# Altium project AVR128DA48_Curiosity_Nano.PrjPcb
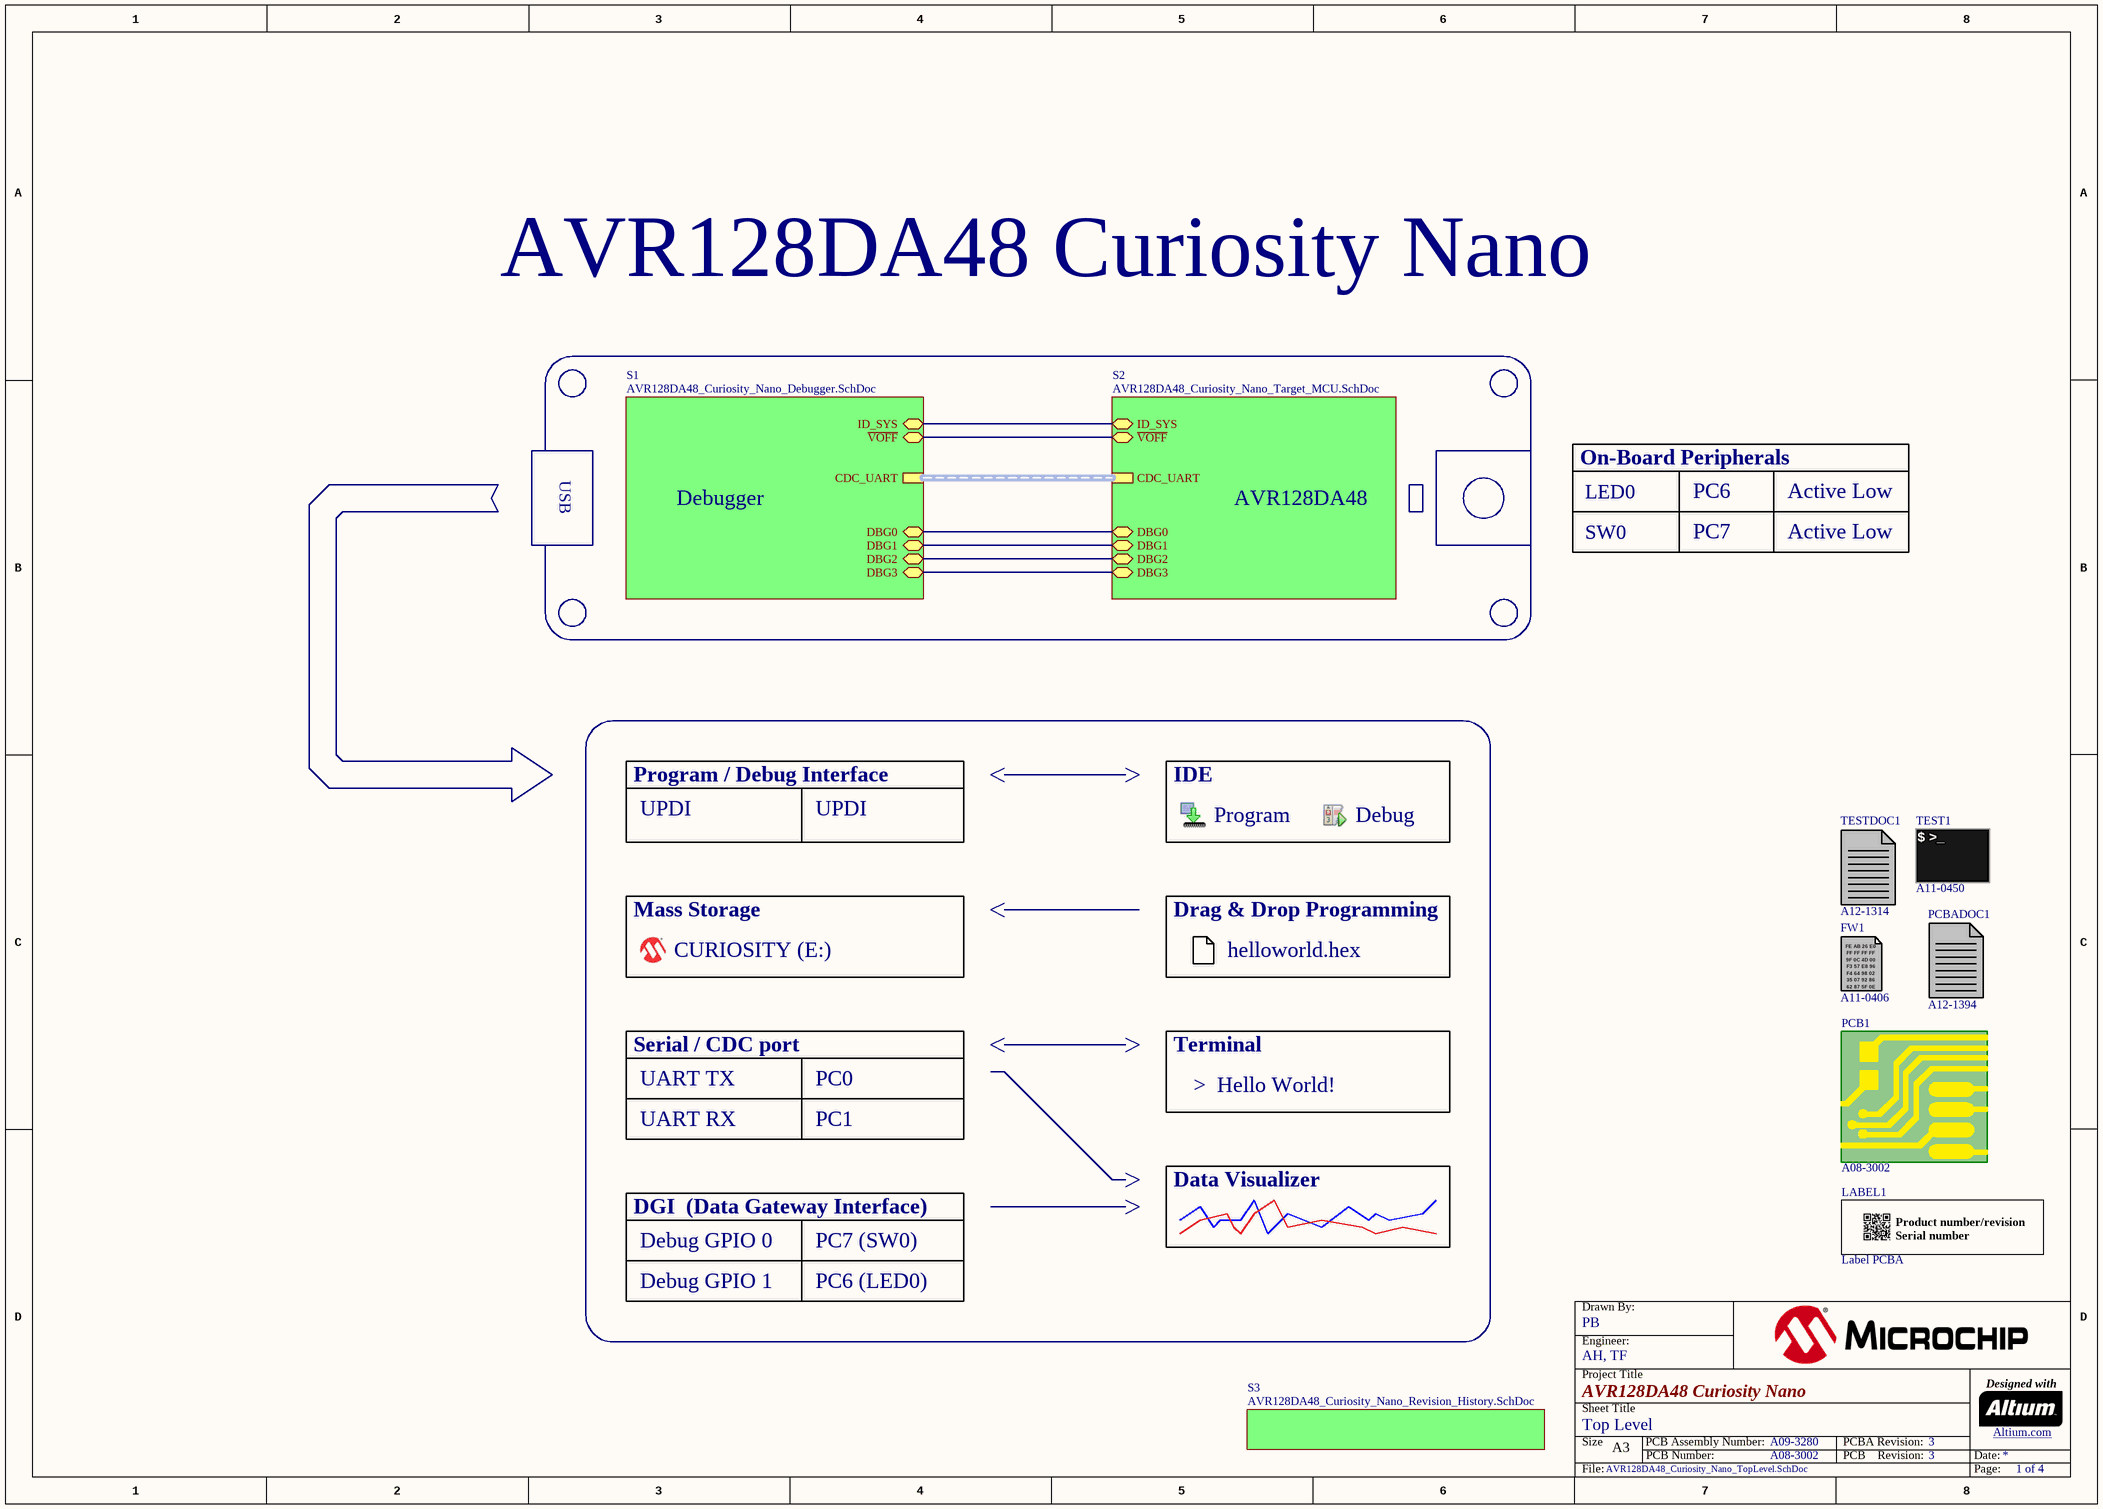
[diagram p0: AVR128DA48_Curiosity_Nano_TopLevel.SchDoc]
4 sheets, 71 parts. Net scope: hierarchical (ports join the sheet entries above them; power ports are global).
Board file: AVR128DA48_Curiosity_Nano.PcbDoc
Sheets:
  AVR128DA48_Curiosity_Nano_TopLevel.SchDoc
    S2 = AVR128DA48_Curiosity_Nano_Target_MCU.SchDoc
    S1 = AVR128DA48_Curiosity_Nano_Debugger.SchDoc
    S3 = AVR128DA48_Curiosity_Nano_Revision_History.SchDoc

## Sheet AVR128DA48_Curiosity_Nano_TopLevel.SchDoc: Top Level
size A3; Organization: Microchip Norway; Address1: Brøsetvegen 164; Address2: 7069 Trondheim; Address3: NORWAY; DocumentNumber: A09-3280; Revision: 3; SheetNumber: 1; SheetTotal: 4; DrawnBy: PB; Engineer: AH, TF; PageSetup: Record=PageOptions¦CenterHorizontal=True¦CenterVertical=True¦PrintScale=1.01¦XCorrection=1.00¦YCorrection=1.00¦PrintKind=1¦BorderSize=5000000¦LeftOffset=0¦BottomOffset=0¦Orientation=2¦PaperLength=1000¦PaperWidth=1000¦Scale=100¦PaperSource=7¦PrintQuality=-4¦MediaType=1¦DitherType=10¦PaperKind=A3 (297 x 420 mm)¦PrintScaleMode=1; ProjectTitle: AVR128DA48 Curiosity Nano; PCBNumber: A08-3002; PCBRevision: 3

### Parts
FW1  AN: A11-0406  (mechanical)
LABEL1  value Label PCBA  [AP8-00317]
PCB1  AN: A08-3002  (mechanical)
PCBADOC1  AN: A12-1394  (mechanical)
TEST1  AN: A11-0450  (mechanical)
TESTDOC1  AN: A12-1314  (hidden comment: Use test fixture A13-0177)  (mechanical)

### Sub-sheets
S1 = AVR128DA48_Curiosity_Nano_Debugger.SchDoc: CDC_UART (harness UART), DBG2 (bidir), DBG1 (bidir), DBG3 (bidir), DBG0 (bidir), ~{VOFF} (bidir), ID_SYS (bidir)
S2 = AVR128DA48_Curiosity_Nano_Target_MCU.SchDoc: DBG0 (bidir), CDC_UART (harness UART), DBG1 (bidir), DBG3 (bidir), DBG2 (bidir), ~{VOFF} (bidir), ID_SYS (bidir)
S3 = AVR128DA48_Curiosity_Nano_Revision_History.SchDoc: no entries

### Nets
DBG0: sheet S2/DBG0, sheet S1/DBG0
DBG1: sheet S2/DBG1, sheet S1/DBG1
DBG2: sheet S2/DBG2, sheet S1/DBG2
DBG3: sheet S2/DBG3, sheet S1/DBG3
ID_SYS: sheet S2/ID_SYS, sheet S1/ID_SYS
~{VOFF}: sheet S2/~{VOFF}, sheet S1/~{VOFF}

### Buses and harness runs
harness sheet S1/CDC_UART = sheet S2/CDC_UART

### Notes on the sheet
- AVR128DA48 Curiosity Nano
- USB
- Debugger
- AVR128DA48
- On-Board Peripherals
- LED0
- PC6
- Active Low
- SW0
- PC7
- Program / Debug Interface
- IDE
- UPDI
- Program
- Debug
- Mass Storage
- Drag & Drop Programming
- CURIOSITY (E:)
- helloworld.hex
- Serial / CDC port
- Terminal
- UART TX
- UART RX
- PC1
- PC0
- >  Hello World!
- Data Visualizer
- DGI  (Data Gateway Interface)
- Debug GPIO 0
- PC7 (SW0)
- Debug GPIO 1
- PC6 (LED0)

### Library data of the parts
FW1 = A11-0406: nEDBG firmware; PartGroup: Software,Firmware,Tools
LABEL1 = A09-0611: PCBA identification label PP Top White Gloss; Manufacturer: ACT Logimark AS; MPN: 505462; PartGroup: Mechanical devices,Packaging materials,Printed Labels,PCBA
PCB1 = A08-3002: AVR128DA48 Curiosity Nano PCB documentation; PartGroup: Mechanical devices,Printed circuit boards
PCBADOC1 = A12-1394: AVR128DA48 Curiosity Nano PCBA documentation; PartGroup: Documentation,PCBA Documents,Atmel; Value: A09-3280 PCBA files
TEST1 = A11-0450: Fixture test for AVR128DA48 Curiosity Nano; PartGroup: Software,Test software,Starter Kit; Value: AVR128DA48 Curiosity Nano test
TESTDOC1 = A12-1314: Generic Test Instructions for Curiosity Nano; PartGroup: Documentation,Procedures,Test Instructions; Value: Curiosity Nano Test Instructions

## Sheet AVR128DA48_Curiosity_Nano_Target_MCU.SchDoc: Target MCU
size A3; Organization: Microchip Norway; Address1: Brøsetvegen 164; Address2: 7069 Trondheim; Address3: NORWAY; DocumentNumber: A09-3280; Revision: 3; SheetNumber: 2; SheetTotal: 4; DrawnBy: PB; Engineer: AH, TF; PageSetup: Record=PageOptions¦CenterHorizontal=True¦CenterVertical=True¦PrintScale=1.01¦XCorrection=1.00¦YCorrection=1.00¦PrintKind=1¦BorderSize=5000000¦LeftOffset=0¦BottomOffset=0¦Orientation=2¦PaperLength=1000¦PaperWidth=1000¦Scale=100¦PaperSource=7¦PrintQuality=-4¦MediaType=1¦DitherType=10¦PaperKind=A3 (297 x 420 mm)¦PrintScaleMode=1; ProjectTitle: AVR128DA48 Curiosity Nano; PCBNumber: A08-3002; PCBRevision: 3
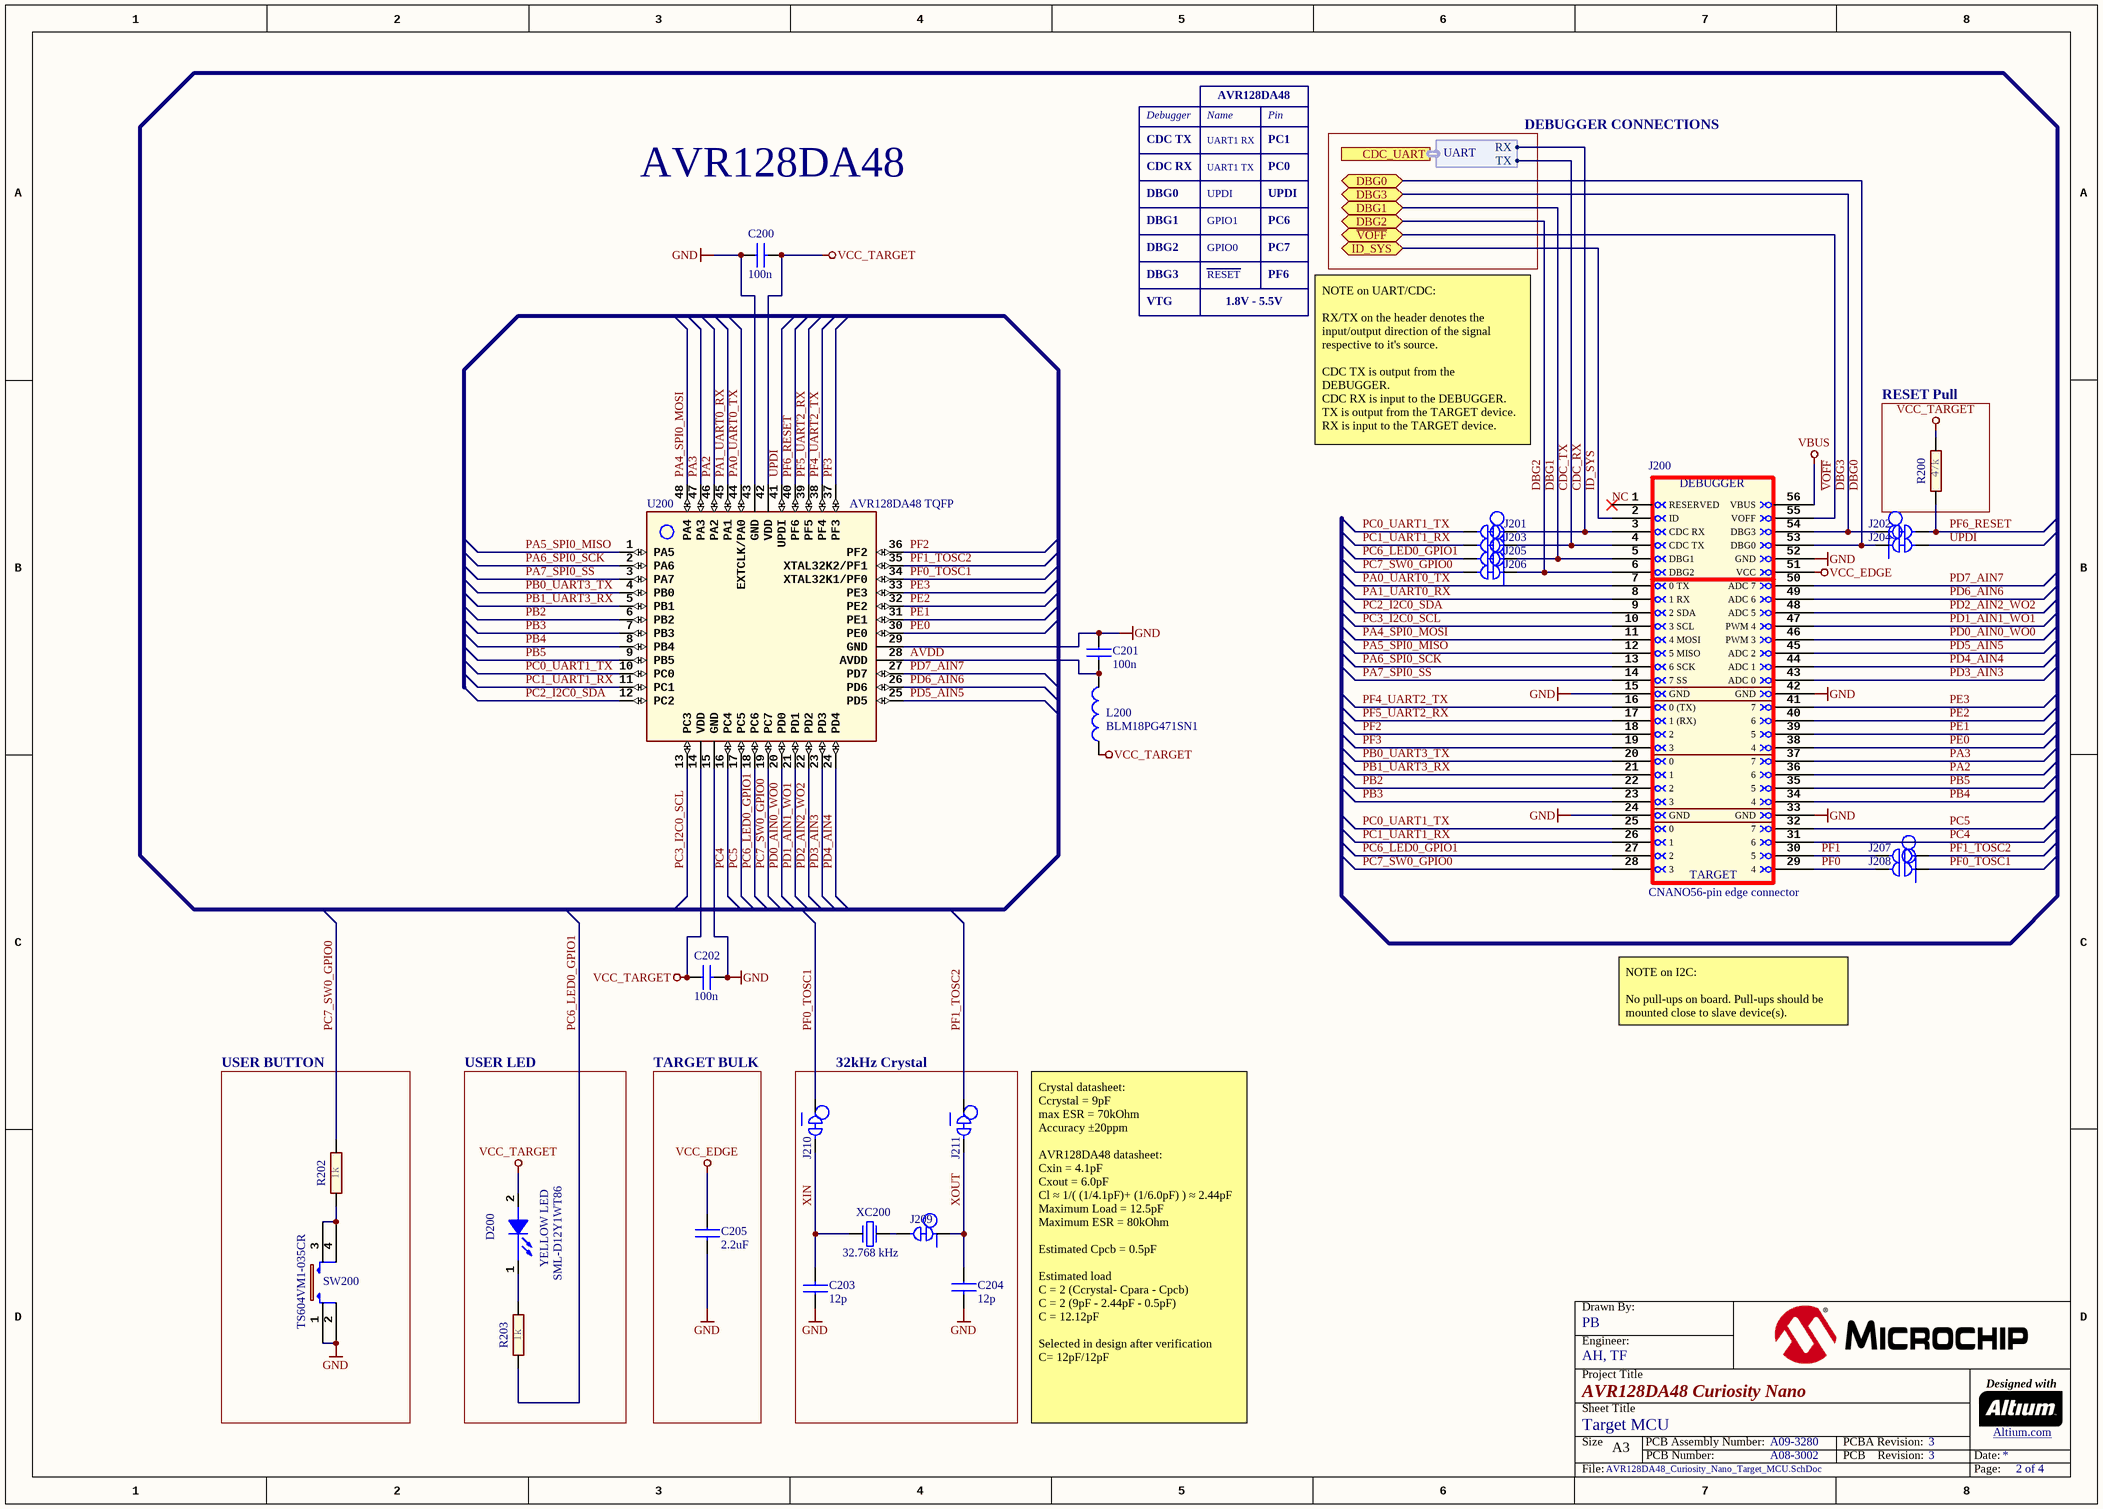
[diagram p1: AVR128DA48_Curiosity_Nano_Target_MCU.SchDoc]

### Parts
C200  value 100n  [AP1-00053]
C201  value 100n  [AP1-00053]
C202  value 100n  [AP1-00053]
C203  value 12p  [AP1-00001]
C204  value 12p  [AP1-00001]
C205  value 2.2uF  [AP1-00053]
D200  value YELLOW LED  MPN: SML-D12Y1WT86  [AP4-00169]
J200  value CNANO56-pin edge connector  [AP8-01100]  (no BOM)
J201  (no value)  [AP8-01166]  (net tie, no BOM)
J202  (no value)  [AP8-01166]  (net tie, no BOM)
J203  (no value)  [AP8-01166]  (net tie, no BOM)
J204  (no value)  [AP8-01166]  (net tie, no BOM)
J205  (no value)  [AP8-01166]  (net tie, no BOM)
J206  (no value)  [AP8-01166]  (net tie, no BOM)
J207  (no value)  [AP9-00172]  (no BOM)
J208  (no value)  [AP9-00172]  (no BOM)
J209  (no value)  [AP8-00595]  (net tie, no BOM)
J210  (no value)  [AP8-01166]  (net tie, no BOM)
J211  (no value)  [AP8-01166]  (net tie, no BOM)
L200  value BLM18PG471SN1  [AP3-00005]
R200  value 47k  [AP2-00011]
R202  value 1k  [AP2-00011]
R203  value 1k  [AP2-00011]
SW200  value TS604VM1-035CR  [AP8-00137]  (hidden comment: Rating: DC 12V 50mA / Max 0.1 ohm contact resistance)
U200  value AVR128DA48 TQFP  [AP6-00357]
XC200  (no value)  [AP7-00069]

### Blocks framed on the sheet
RESET Pull: R200
USER BUTTON: R202 SW200
USER LED: D200 R203
TARGET BULK: C205
32kHz Crystal: C203 C204 J209-J211 XC200

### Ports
CDC_UART (harness UART), DBG0 (bidir), DBG1 (bidir), DBG2 (bidir), DBG3 (bidir), ID_SYS (bidir), ~{VOFF} (bidir)

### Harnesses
UART: TX, RX

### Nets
GND: C200.1 C201.1 C202.2 C203.1 C204.2 C205.2 J200.15(GND) J200.24(GND) J200.33(GND) J200.42(GND) J200.52(GND) SW200.1 SW200.2 U200.15(GND) U200.29(GND) U200.43(GND)
VBUS: J200.56(VBUS)
VCC_EDGE: C205.1 J200.51(VCC)
VCC_TARGET: C200.2 C202.1 D200.2(ANODE) L200.1 R200.1 U200.14(VDD) U200.42(VDD)
AVDD: C201.2 L200.2 U200.28(AVDD)
CDC_RX: J200.3(CDC_RX) J201.1 ; port CDC_UART.RX
CDC_TX: J200.4(CDC_TX) J203.1 ; port CDC_UART.TX
DBG0: J200.53(DBG0) J204.1 ; port DBG0
DBG1: J200.5(DBG1) J205.1 ; port DBG1
DBG2: J200.6(DBG2) J206.1 ; port DBG2
DBG3: J200.54(DBG3) J202.1 ; port DBG3
ID_SYS: J200.2(ID) ; port ID_SYS
NC: J200.1(RESERVED)
PA0_UART0_TX: J200.7(0_TX) U200.44(EXTCLK/PA0)
PA1_UART0_RX: J200.8(1_RX) U200.45(PA1)
PA2: J200.36(6) U200.46(PA2)
PA3: J200.37(7) U200.47(PA3)
PA4_SPI0_MOSI: J200.11(4_MOSI) U200.48(PA4)
PA5_SPI0_MISO: J200.12(5_MISO) U200.1(PA5)
PA6_SPI0_SCK: J200.13(6_SCK) U200.2(PA6)
PA7_SPI0_SS: J200.14(7_SS) U200.3(PA7)
PB0_UART3_TX: J200.20(0) U200.4(PB0)
PB1_UART3_RX: J200.21(1) U200.5(PB1)
PB2: J200.22(2) U200.6(PB2)
PB3: J200.23(3) U200.7(PB3)
PB4: J200.34(4) U200.8(PB4)
PB5: J200.35(5) U200.9(PB5)
PC0_UART1_TX: J200.25(0) J201.2 U200.10(PC0)
PC1_UART1_RX: J200.26(1) J203.2 U200.11(PC1)
PC2_I2C0_SDA: J200.9(2_SDA) U200.12(PC2)
PC3_I2C0_SCL: J200.10(3_SCL) U200.13(PC3)
PC4: J200.31(6) U200.16(PC4)
PC5: J200.32(7) U200.17(PC5)
PC6_LED0_GPIO1: J200.27(2) J205.2 R203.1 U200.18(PC6)
PC7_SW0_GPIO0: J200.28(3) J206.2 R202.1 U200.19(PC7)
PD0_AIN0_WO0: J200.46(PWM_3) U200.20(PD0)
PD1_AIN1_WO1: J200.47(PWM_4) U200.21(PD1)
PD2_AIN2_WO2: J200.48(ADC_5) U200.22(PD2)
PD3_AIN3: J200.43(ADC_0) U200.23(PD3)
PD4_AIN4: J200.44(ADC_1) U200.24(PD4)
PD5_AIN5: J200.45(ADC_2) U200.25(PD5)
PD6_AIN6: J200.49(ADC_6) U200.26(PD6)
PD7_AIN7: J200.50(ADC_7) U200.27(PD7)
PE0: J200.38(4) U200.30(PE0)
PE1: J200.39(5) U200.31(PE1)
PE2: J200.40(6) U200.32(PE2)
PE3: J200.41(7) U200.33(PE3)
PF0: J200.29(4) J208.2
PF0_TOSC1: J208.1 J210.1 U200.34(XTAL32K1/PF0)
PF1: J200.30(5) J207.2
PF1_TOSC2: J207.1 J211.1 U200.35(XTAL32K2/PF1)
PF2: J200.18(2) U200.36(PF2)
PF3: J200.19(3) U200.37(PF3)
PF4_UART2_TX: J200.16(0_(TX)) U200.38(PF4)
PF5_UART2_RX: J200.17(1_(RX)) U200.39(PF5)
PF6_RESET: J202.2 R200.2 U200.40(PF6)
UPDI: J204.2 U200.41(UPDI)
~{VOFF}: J200.55(VOFF) ; port ~{VOFF}
XIN: C203.2 J210.2 XC200.2
XOUT: C204.1 J209.1 J211.2
NetD200_1: D200.1(CATHODE) R203.2
NetJ209_2: J209.2 XC200.1
NetR202_2: R202.2 SW200.3 SW200.4

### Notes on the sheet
- AVR128DA48
- Debugger
- CDC TX
- CDC RX
- UART1 RX
- UART1 TX
- Name
- PC0
- PC1
- Pin
- DEBUGGER CONNECTIONS
- DBG0
- DBG1
- UPDI
- GPIO1
- PC6
- DBG2
- DBG3
- VTG
- GPIO0
- RESET
- 1.8V - 5.5V
- PC7
- PF6
- NOTE on UART/CDC:
  RX/TX on the header denotes the input/output direction of the signal respective to it's source.
  CDC TX is output from the DEBUGGER.
  CDC RX is input to the DEBUGGER.
  TX is output from the TARGET device.
  RX is input to the TARGET device.
- NOTE on I2C:
  No pull-ups on board. Pull-ups should be mounted close to slave device(s).
- 32.768 kHz
- Crystal datasheet:
  Ccrystal = 9pF
  max ESR = 70kOhm
  Accuracy ±20ppm
  AVR128DA48 datasheet:
  Cxin = 4.1pF
  Cxout = 6.0pF
  Cl ≈ 1/( (1/4.1pF)+ (1/6.0pF) ) ≈ 2.44pF
  Maximum Load = 12.5pF
  Maximum ESR = 80kOhm
  Estimated Cpcb = 0.5pF
  Estimated load
  C = 2 (Ccrystal- Cpara - Cpcb)
  C = 2 (9pF - 2.44pF - 0.5pF)
  C = 12.12pF
  Selected in design after verification
  C= 12pF/12pF

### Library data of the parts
C200-C202 = A01-0246: Ceramic capacitor, SMD 0402, X7R, 16V, +/-10%; Manufacturer: Kemet; MPN: C0402C104K4RACTU; PartGroup: Capacitors,Ceramic,SMD 0402; TemperatureRange: -55 - +125 deg C
C203 C204 = A01-0016: Ceramic capacitor, SMD 0402, NP0, 50V, +/-5%; PartGroup: Capacitors,Ceramic,SMD 0402; Manufacturer: Kemet; MPN: C0402C120J5GAC7867; TemperatureRange: -55 - +125 deg C
C205 = A01-0493: CAP CER 2.2UF 10V 10% X5R 0402; PartGroup: Capacitors,Ceramic,SMD 0402; Manufacturer: TDK; MPN: C1005X5R1A225K; Tolerance: +/-10%; TemperatureRange: -55 to 85C
D200 = A10-0218: LED, SMD 0603, Yellow, Wave length=590nm, 100mcd @ (20mA, 2.2Vf) rohm; PartGroup: Opto,LEDs,SMD; TemperatureRange: -40 to +85
J200 = A08-2840: Curiosity Nano 56-pin edge connector with castellations, 100-mil pitch.; PartGroup: Mechanical devices,Connectors,Pin headers
J201-J206 J210 J211 = A08-2981: Closed Link 0402 w/50mil hole; PartGroup: Mechanical devices,PCB implemented components
J207 J208 = A08-2866: 1x1mm, Round Strap, Open, no frame; PartGroup: Mechanical devices,PCB implemented components; Value: SOLDER-STRAP_OPEN
J209 = A08-1454: Closed Link 0402; PartGroup: Mechanical devices,PCB implemented components
L200 = A03-0035: SMD RF inductor 0603. Z=470Ohm (@100MHz), Max R(dc)=0.20Ohm, Max current=1A; PartGroup: Inductors,EMI; Manufacturer: Murata; TemperatureRange: -55
R200 = A02-0252: Thick film resistor, SMD 0402, 1/16W, 1%; Manufacturer: KOA; MPN: RK73H1ETTP4702F; PartGroup: Resistors,SMD,0402 1%; TemperatureRange: -55 - +125 deg C
R202 = A02-0212: Thick film resistor, SMD 0402, 1/16W, 1%; Manufacturer: ASJ Holdings; MPN: CR10-1001-FK; PartGroup: Resistors,SMD,0402 1%; TemperatureRange: -55 - +125 deg C
R203 = A02-0212: Thick film resistor, SMD 0402, 1/16W, 1%; PartGroup: Resistors,SMD,0402 1%; Manufacturer: ASJ Holdings; MPN: CR10-1001-FK; TemperatureRange: -55 - +125 deg C
SW200 = A08-2830: SWITCH, SMD, 260gf, 6.4mm X 6.2mm; PartGroup: Mechanical devices,Switches,SMD; Manufacturer: Dailywell Electronics Co.LTD; MPN: TS604VM1-035CR-R; TemperatureRange: -40 - +85 deg C
U200 = A06-1684: 8-bit RISC MCU, 128K Flash, 48pin TQFP, 7x7mm, 0.5m pitch package; PartGroup: Integrated Circuits,MCU, MPU, DSP,AVR MCU; Manufacturer: Microchip; MPN: AVR128DA48T-I/PT; TemperatureRange: -40°C to +125°C
XC200 = A07-0170: Crystal, 32.768kHz, CL=9.0pF, ESR=70kOhm, SMD  LxW=3.2 x 1.5mm, 20ppm; PartGroup: Frequency devices,Crystals,SMD; Manufacturer: Abracon; MPN: ABS07-32.768kHz-9-T; TemperatureRange: -40°C to + 85°C

## Sheet AVR128DA48_Curiosity_Nano_Debugger.SchDoc: Debugger
size A3; Organization: Microchip Norway; Address1: Brøsetvegen 164; Address2: 7069 Trondheim; Address3: NORWAY; DocumentNumber: A09-3280; Revision: 3; SheetNumber: 3; SheetTotal: 4; DrawnBy: PB; Engineer: AH, TF; PageSetup: Record=PageOptions¦CenterHorizontal=True¦CenterVertical=True¦PrintScale=1.01¦XCorrection=1.00¦YCorrection=1.00¦PrintKind=1¦BorderSize=5000000¦LeftOffset=0¦BottomOffset=0¦Orientation=2¦PaperLength=1000¦PaperWidth=1000¦Scale=100¦PaperSource=7¦PrintQuality=-4¦MediaType=1¦DitherType=10¦PaperKind=A3 (297 x 420 mm)¦PrintScaleMode=1; ProjectTitle: AVR128DA48 Curiosity Nano; PCBNumber: A08-3002; PCBRevision: 3
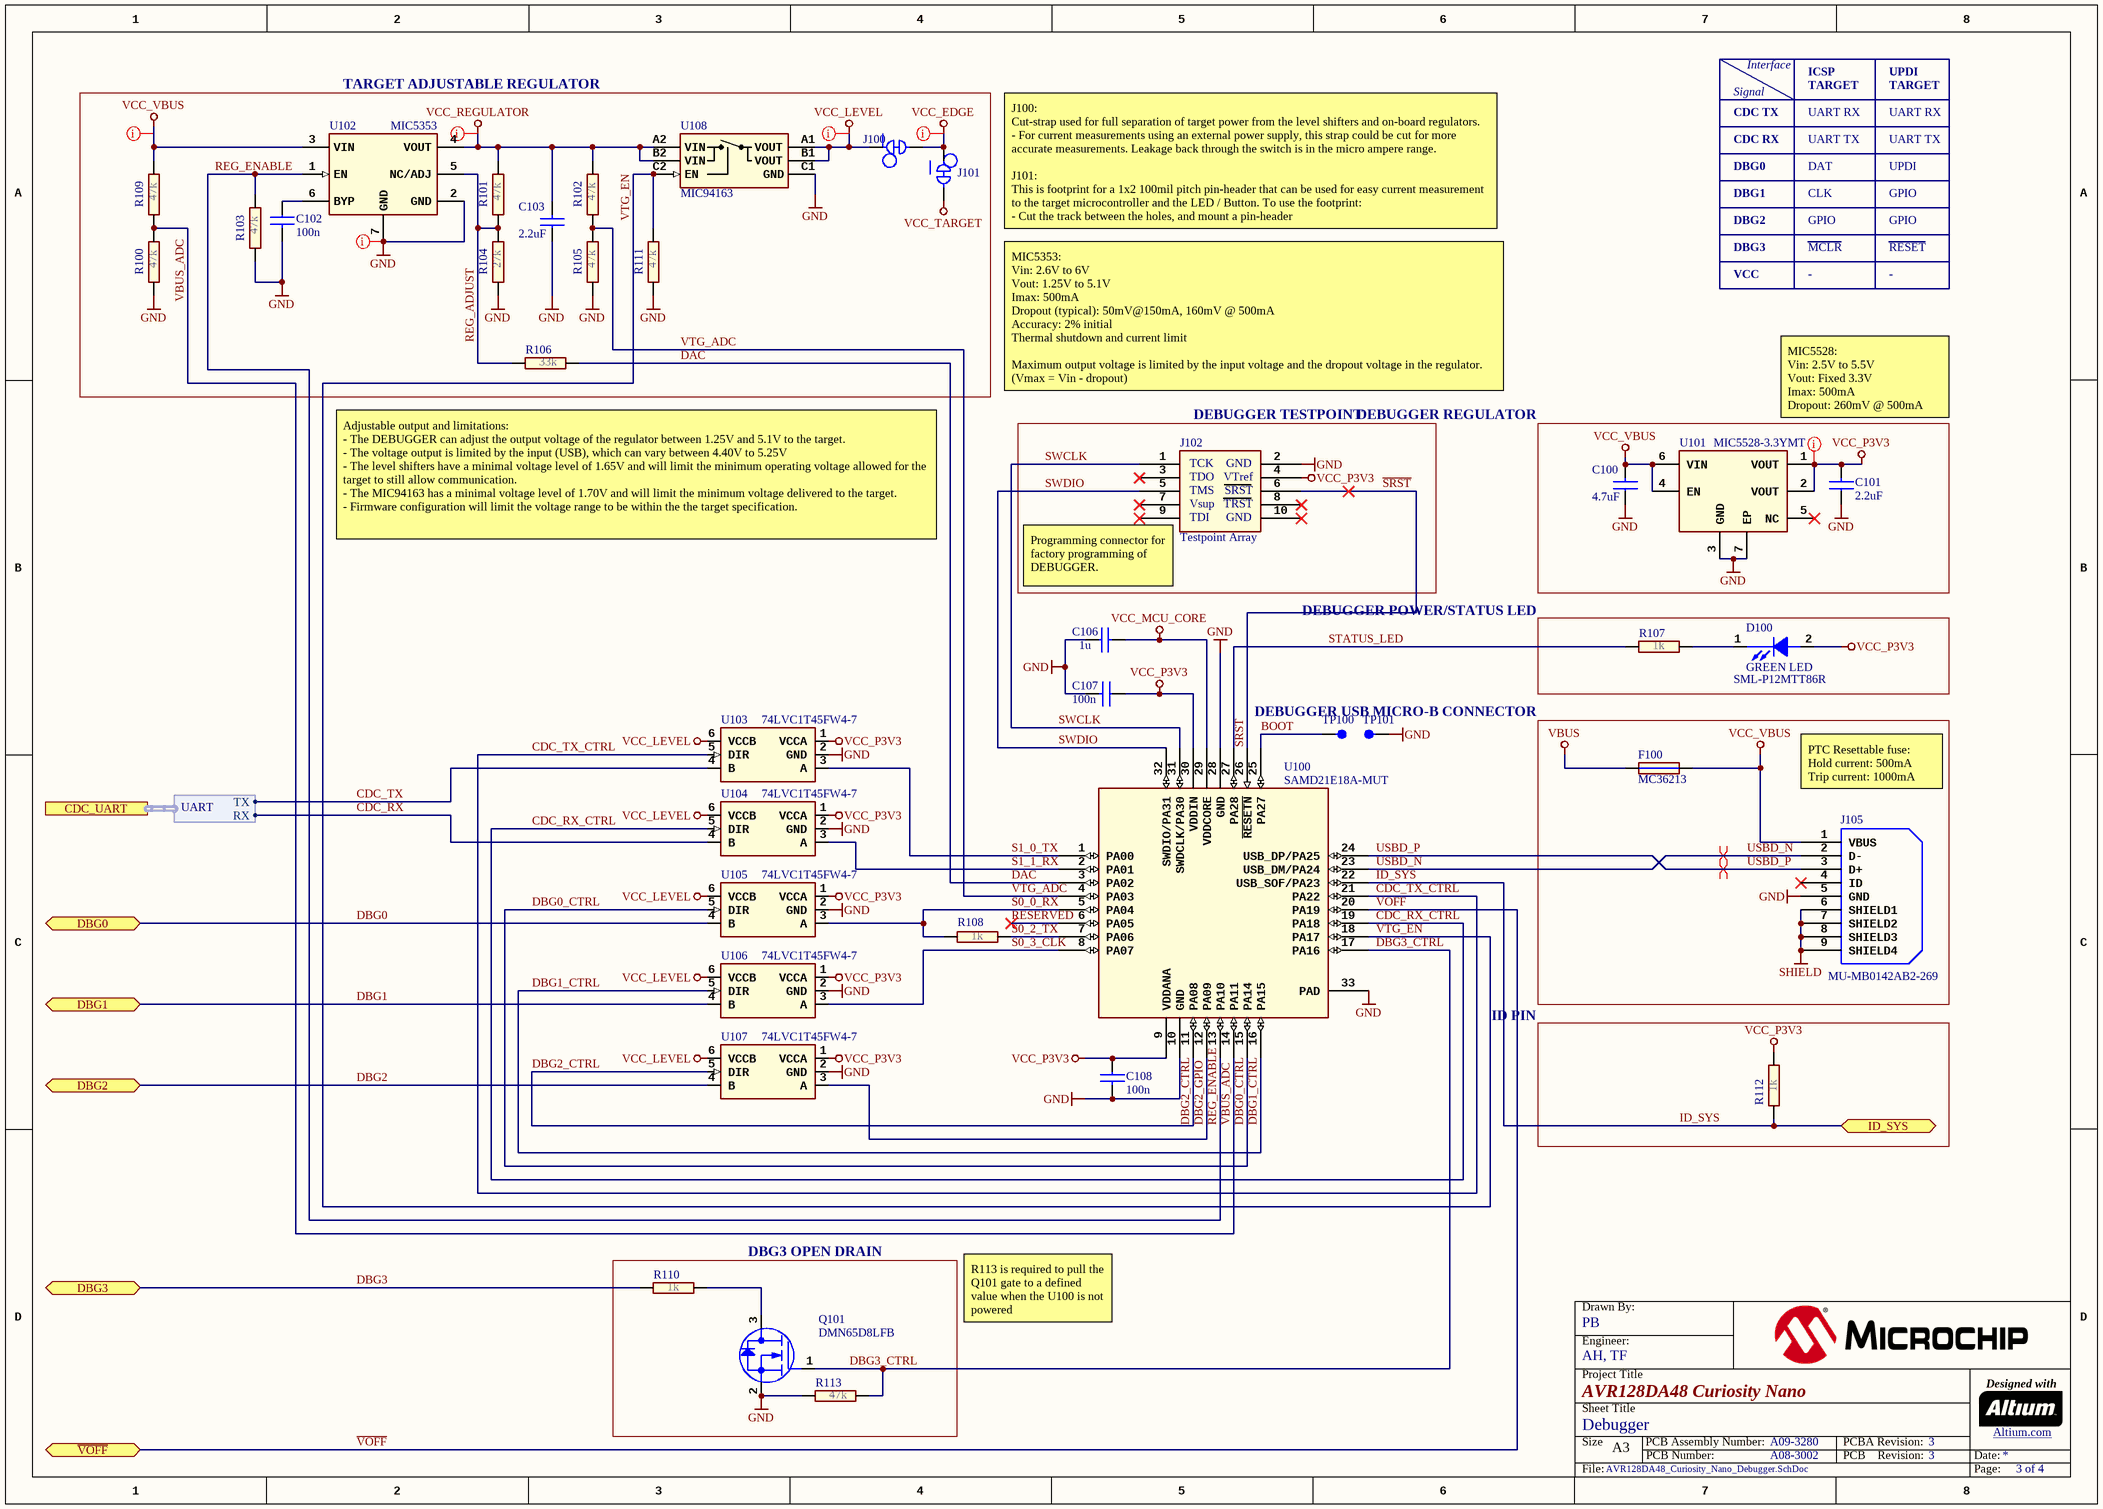
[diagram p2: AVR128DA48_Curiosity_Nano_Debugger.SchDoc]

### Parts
C100  value 4.7uF  [AP1-00039]
C101  value 2.2uF  [AP1-00053]  (hidden comment: Farnell no: 1288200)
C102  value 100n  [AP1-00053]
C103  value 2.2uF  [AP1-00053]
C106  value 1u  [AP1-00053]
C107  value 100n  [AP1-00053]
C108  value 100n  [AP1-00053]
D100  value GREEN LED  MPN: SML-P12MTT86R  [AP4-00160]
F100  value MC36213  [AP2-00002]  (hidden comment: Farnell no: 1861197)
J100  (no value)  [AP8-00595]  (net tie, no BOM)
J101  (no value)  [AP8-01183]  (net tie, no BOM)
J102  value Testpoint Array  [AP8-00997]  (no BOM)
J105  value MU-MB0142AB2-269  [AP8-01099]
Q101  value DMN65D8LFB  [AP5-00056]
R100  value 47k  [AP2-00011]
R101  value 47k  [AP2-00011]
R102  value 47k  [AP2-00011]
R103  value 47k  [AP2-00011]
R104  value 27k  [AP2-00011]
R105  value 47k  [AP2-00011]
R106  value 33k  [AP2-00011]
R107  value 1k  [AP2-00011]
R108  value 1k  [AP2-00011]
R109  value 47k  [AP2-00011]
R110  value 1k  [AP2-00011]
R111  value 47k  [AP2-00011]
R112  value 1k  [AP2-00011]
R113  value 47k  [AP2-00011]
TP100  PCB implemented component.  [AP8-00870]  (value not drawn)  (no BOM)
TP101  PCB implemented component.  [AP8-00870]  (value not drawn)  (no BOM)
U100  value SAMD21E18A-MUT  [AP6-00418]  (hidden comment: QFN32)
U101  value MIC5528-3.3YMT  [AP6-00481]
U102  value MIC5353  [AP6-00504]  (hidden comment: Marking code: AAR)
U103  value 74LVC1T45FW4-7  [AP6-00505]
U104  value 74LVC1T45FW4-7  [AP6-00505]
U105  value 74LVC1T45FW4-7  [AP6-00505]
U106  value 74LVC1T45FW4-7  [AP6-00505]
U107  value 74LVC1T45FW4-7  [AP6-00505]
U108  value MIC94163  [AP6-00513]

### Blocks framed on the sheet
TARGET ADJUSTABLE REGULATOR: C102 C103 J100 J101 R100-R106 R109 R111 U102 U108
DEBUGGER TESTPOINT: J102
DEBUGGER REGULATOR: C100 C101 U101
DEBUGGER POWER/STATUS LED: D100 R107
DEBUGGER USB MICRO-B CONNECTOR: F100 J105
ID PIN: R112
DBG3 OPEN DRAIN: Q101 R110 R113

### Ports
CDC_UART (harness UART), DBG0 (bidir), DBG1 (bidir), DBG2 (bidir), DBG3 (bidir), ID_SYS (bidir), ~{VOFF} (bidir)

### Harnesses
UART: RX, TX

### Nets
GND: C100.1 C101.1 C102.2 C103.1 C106.1 C107.2 C108.2 J102.2 J105.5(GND) Q101.2(S) R100.2 R103.2 R104.1 R105.1 R111.2 R113.1 TP101.1 U100.10(GND) U100.28(GND) U100.33(PAD) U101.3(GND) U101.7(EP) U102.2(GND) U102.7(GND) U103.2(GND) U104.2(GND) U105.2(GND) U106.2(GND) U107.2(GND) U108.C1(GND)
SHIELD: J105.6(SHIELD1) J105.7(SHIELD2) J105.8(SHIELD3) J105.9(SHIELD4)
VBUS: F100.1
VCC_EDGE: J100.2 J101.1
VCC_LEVEL: J100.1 U103.6(VCCB) U104.6(VCCB) U105.6(VCCB) U106.6(VCCB) U107.6(VCCB) U108.A1(VOUT) U108.B1(VOUT)
VCC_MCU_CORE: C106.2 U100.29(VDDCORE)
VCC_P3V3: C101.2 C107.1 C108.1 D100.2(ANODE) J102.4 R112.1 U100.9(VDDANA) U100.30(VDDIN) U101.1(VOUT) U101.2(VOUT) U103.1(VCCA) U104.1(VCCA) U105.1(VCCA) U106.1(VCCA) U107.1(VCCA)
VCC_REGULATOR: C103.2 R101.1 R102.2 U102.4(VOUT) U108.A2(VIN) U108.B2(VIN)
VCC_TARGET: J101.2
VCC_VBUS: C100.2 F100.2 J105.1(VBUS) R109.2 U101.4(EN) U101.6(VIN) U102.3(VIN)
BOOT: TP100.1 U100.25(PA27)
CDC_RX: U104.4(B) ; port CDC_UART.RX
CDC_RX_CTRL: U100.19(PA18) U104.5(DIR)
CDC_TX: U103.4(B) ; port CDC_UART.TX
CDC_TX_CTRL: U100.21(PA22) U103.5(DIR)
DAC: R106.2 U100.3(PA02)
DBG0: U105.4(B) ; port DBG0
DBG0_CTRL: U100.15(PA14) U105.5(DIR)
DBG1: U106.4(B) ; port DBG1
DBG1_CTRL: U100.16(PA15) U106.5(DIR)
DBG2: U107.4(B) ; port DBG2
DBG2_CTRL: U100.11(PA08) U107.5(DIR)
DBG2_GPIO: U100.12(PA09) U107.3(A)
DBG3: R110.2 ; port DBG3
DBG3_CTRL: Q101.1(G) R113.2 U100.17(PA16)
ID_SYS: R112.2 U100.22(USB_SOF/PA23) ; port ID_SYS
REG_ADJUST: R101.2 R104.2 R106.1 U102.5(NC/ADJ)
REG_ENABLE: R103.1 U100.13(PA10) U102.1(EN)
RESERVED: U100.6(PA05)
S0_0_RX: R108.1 U100.5(PA04) U105.3(A)
S0_2_TX: R108.2 U100.7(PA06)
S0_3_CLK: U100.8(PA07) U106.3(A)
S1_0_TX: U100.1(PA00) U103.3(A)
S1_1_RX: U100.2(PA01) U104.3(A)
~{SRST}: J102.6 U100.26(~{RESETN})
STATUS_LED: R107.2 U100.27(PA28)
SWCLK: J102.1 U100.31(SWDCLK/PA30)
SWDIO: J102.5 U100.32(SWDIO/PA31)
USBD_N: J105.2(D-) U100.23(USB_DM/PA24)
USBD_P: J105.3(D+) U100.24(USB_DP/PA25)
~{VOFF}: U100.20(PA19) ; port ~{VOFF}
VBUS_ADC: R100.1 R109.1 U100.14(PA11)
VTG_ADC: R102.1 R105.2 U100.4(PA03)
VTG_EN: R111.1 U100.18(PA17) U108.C2(EN)
NetC102_1: C102.1 U102.6(BYP)
NetD100_1: D100.1(CATHODE) R107.1
NetQ101_3: Q101.3(D) R110.1

Not connected (* = marked no-connect by the designer): J102 3* 7* 8* 9* 10*; J105 4(ID)*; U101 5(NC)*

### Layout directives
differential pair: USBD_N, USBD_P
net class Power: GND, VCC_EDGE, VCC_LEVEL, VCC_P3V3, VCC_REGULATOR, VCC_VBUS

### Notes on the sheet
- Signal
- Interface
- ICSP
- TARGET
- UPDI
- DBG0
- CDC TX
- CDC RX
- DAT
- UART RX
- UART TX
- J100:
  Cut-strap used for full separation of target power from the level shifters and on-board regulators.
  - For current measurements using an external power supply, this strap could be cut for more accurate measurements. Leakage back through the switch is in the micro ampere range.
  J101:
  This is footprint for a 1x2 100mil pitch pin-header that can be used for easy current measurement to the target microcontroller and the LED / Button. To use the footprint:
  - Cut the track between the holes, and mount a pin-header
- DBG1
- DBG2
- CLK
- GPIO
- DBG3
- VCC
- MCLR
- -
- RESET
- MIC5353:
  Vin: 2.6V to 6V
  Vout: 1.25V to 5.1V
  Imax: 500mA
  Dropout (typical): 50mV@150mA, 160mV @ 500mA
  Accuracy: 2% initial
  Thermal shutdown and current limit
  Maximum output voltage is limited by the input voltage and the dropout voltage in the regulator.
  (Vmax = Vin - dropout)
- MIC5528:
  Vin: 2.5V to 5.5V
  Vout: Fixed 3.3V
  Imax: 500mA
  Dropout: 260mV @ 500mA
- (near R106) Adjustable output and limitations:
  - The DEBUGGER can adjust the output voltage of the regulator between 1.25V and 5.1V to the target.
  - The voltage output is limited by the input (USB), which can vary between 4.40V to 5.25V
  - The level shifters have a minimal voltage level of 1.65V and will limit the minimum operating voltage allowed for the target to still allow communication.
  - The MIC94163 has a minimal voltage level of 1.70V and will limit the minimum voltage delivered to the target.
  - Firmware configuration will limit the voltage range to be within the the target specification.
- (near J102) Programming connector for factory programming of DEBUGGER.
- PTC Resettable fuse:
  Hold current: 500mA
  Trip current: 1000mA
- R113 is required to pull the Q101 gate to a defined value when the U100 is not powered

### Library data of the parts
C100 = A01-0377: Ceramic capacitor, SMD 0603, X5R, 10V, 10% (de31036); PartGroup: Capacitors,Ceramic,SMD 0603; Manufacturer: WALSIN Technology Corporation; MPN: 0603X475K100CT; TemperatureRange: -55 - +85 deg C
C101 = A01-0300: Ceramic capacitor, SMD 0402, X5R, 6.3V, +/-20%; PartGroup: Capacitors,Ceramic,SMD 0402; Manufacturer: Kemet; MPN: C0402C225M9PAC; Tolerance: Â±20%; TemperatureRange: -55Â°C to +85Â°C
C102 C107 C108 = A01-0246: Ceramic capacitor, SMD 0402, X7R, 16V, +/-10%; PartGroup: Capacitors,Ceramic,SMD 0402; Manufacturer: Kemet; MPN: C0402C104K4RACTU; TemperatureRange: -55 - +125 deg C
C103 = A01-0493: as C205 on sheet AVR128DA48_Curiosity_Nano_Target_MCU
C106 = A01-0286: Ceramic capacitor, SMD 0402, X5R, 6.3V, +/-10% (de26942); PartGroup: Capacitors,Ceramic,SMD 0402; Manufacturer: Kemet; MPN: C0402C105K9PAC; TemperatureRange: -55 to 85 deg C
D100 = A10-0213: LED, SMD 0402, Green, Wave length=569nm, 2.1mcd @ (1mA, 1.9Vf)rohm; PartGroup: Opto,LEDs,SMD; TemperatureRange: -40 to +85
F100 = A02-0622: Resetable PTC fuse, Ih = 0.5A, It = 1.0A, 0805 package; PartGroup: Resistors,Resettable fuses,SMD; Manufacturer: Multicomp; TemperatureRange: -40°C to + 85°C
J100 = A08-1454: as J209 on sheet AVR128DA48_Curiosity_Nano_Target_MCU
J101 = A08-3029: Closed Link with w/hole for 1x2 100mil header; PartGroup: Mechanical devices,PCB implemented components; Value: Closed Link 1x2 100mil header
J102 = A08-2568: 10-pin Testpoint Array, 0.8mm Pad, 1.27mm Pitch; PartGroup: Mechanical devices,PCB implemented components,PCB plane connectors
J105 = A08-2839: USB micro AB, Surface mount signals and DIP shield; PartGroup: Mechanical devices,Connectors,USB; Manufacturer: Allen Creations Corp.; TemperatureRange: -30Â°C to +80Â°C
Q101 = A05-0180: N-channel MOSFET, DFN1006-3 (SOT883), 60V, 330mA, 4Ohm; PartGroup: Transistors,Small signal FET,SMD; Manufacturer: Diodes Incorporated; MPN: DMN65D8LFB-7; TemperatureRange: -55Â°C to +150Â°C
R100-R102 R105 R109 R111 R113 = A02-0252: as R200 on sheet AVR128DA48_Curiosity_Nano_Target_MCU
R103 = A02-0252: Thick film resistor, SMD 0402, 1/16W, 1%; PartGroup: Resistors,SMD,0402 1%; Manufacturer: KOA; MPN: RK73H1ETTP4702F; TemperatureRange: -55 - +125 deg C
R104 = A02-0246: Thick film resistor, SMD 0402, 1/16W, 1%; Manufacturer: Yageo; MPN: RC0402FR-0727KL; PartGroup: Resistors,SMD,0402 1%; TemperatureRange: -55 - +125 deg C
R106 = A02-0248: Thick film resistor, SMD 0402, 1/16W, 1%; Manufacturer: ASJ Holdings; MPN: CR10-3302-FK; PartGroup: Resistors,SMD,0402 1%; TemperatureRange: -55 - +125 deg C
R107 R108 R110 R112 = A02-0212: as R203 on sheet AVR128DA48_Curiosity_Nano_Target_MCU
TP100 TP101 = A08-2176: SMD Test point - 0.8mm; PartGroup: Mechanical devices,Connectors,Test points
U100 = A06-1205: 32-bit RISC MCU 32pin; PartGroup: Integrated Circuits,MCU, MPU, DSP,ARM MCU; Manufacturer: Microchip; MPN: ATSAMD21E18A-MUT; TemperatureRange: -40Â°C to +85Â°C
U101 = A06-1475: LDO 3.3V 0.5A 6TDFN; PartGroup: Integrated Circuits,Regulators,Linear; Manufacturer: Microchip; MPN: MIC5528-3.3YMT-T5; TemperatureRange: -40Â°C ~ 125Â°C
U102 = A06-1578: 500mA Ultra Low Dropout LDO regulator, 2% accuracy, 1.6x1.6mm MLF; PartGroup: Integrated Circuits,Regulators,Linear; Manufacturer: Microchip; MPN: MIC5353YMT-TR; TemperatureRange: -40Â°C to +125Â°C
U103-U107 = A06-1580: Single-Bit Dual-Supply Transceive, 1.65-5.5 Translation and 3-State Outputs; PartGroup: Integrated Circuits,Interface ICs,Level translators; Manufacturer: Diodes Incorporated; TemperatureRange: -40C - 125C
U108 = A06-1613: Loadswitch, Rds(on) = 14.5mohm, 1.0mm x 1.5mm WLCSP, reverse blocking; PartGroup: Integrated Circuits,General linear,Analog switch, bus switch and MUX; Manufacturer: Microchip; MPN: MIC94163YCS-TR; TemperatureRange: -40Â°C to +125Â°C

## Sheet AVR128DA48_Curiosity_Nano_Revision_History.SchDoc: Revision History
size A3; Organization: Microchip Norway; Address1: Brøsetvegen 164; Address2: 7069 Trondheim; Address3: NORWAY; DocumentNumber: A09-3280; Revision: 3; SheetNumber: 4; SheetTotal: 4; DrawnBy: PB; Engineer: AH, TF; PageSetup: Record=PageOptions¦CenterHorizontal=True¦CenterVertical=True¦PrintScale=1.01¦XCorrection=1.00¦YCorrection=1.00¦PrintKind=1¦BorderSize=5000000¦LeftOffset=0¦BottomOffset=0¦Orientation=2¦PaperLength=1000¦PaperWidth=1000¦Scale=100¦PaperSource=7¦PrintQuality=-4¦MediaType=1¦DitherType=10¦PaperKind=A3 (297 x 420 mm)¦PrintScaleMode=1; ProjectTitle: AVR128DA48 Curiosity Nano; PCBNumber: A08-3002; PCBRevision: 3
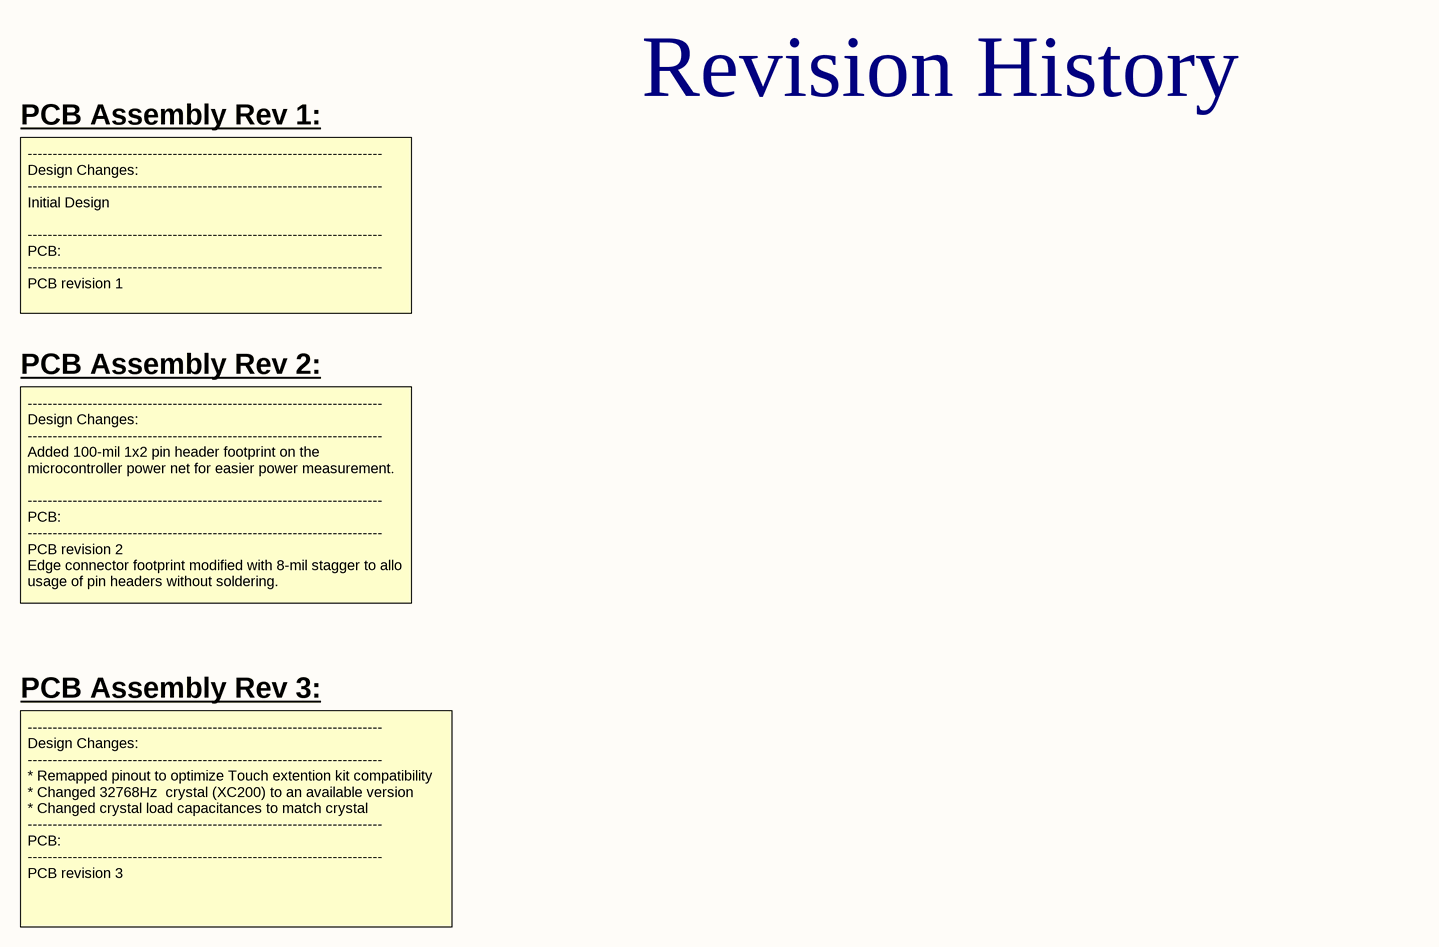
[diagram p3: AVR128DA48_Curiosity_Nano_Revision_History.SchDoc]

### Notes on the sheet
- PCB Assembly Rev 1:
- Revision History
- -----------------------------------------------------------------------
  Design Changes:
  -----------------------------------------------------------------------
  Initial Design
  -----------------------------------------------------------------------
  PCB:
  -----------------------------------------------------------------------
  PCB revision 1
- PCB Assembly Rev 2:
- -----------------------------------------------------------------------
  Design Changes:
  -----------------------------------------------------------------------
  Added 100-mil 1x2 pin header footprint on the microcontroller power net for easier power measurement.
  -----------------------------------------------------------------------
  PCB:
  -----------------------------------------------------------------------
  PCB revision 2
  Edge connector footprint modified with 8-mil stagger to allo usage of pin headers without soldering.
- PCB Assembly Rev 3:
- -----------------------------------------------------------------------
  Design Changes:
  -----------------------------------------------------------------------
  * Remapped pinout to optimize Touch extention kit compatibility
  * Changed 32768Hz  crystal (XC200) to an available version
  * Changed crystal load capacitances to match crystal
  -----------------------------------------------------------------------
  PCB:
  -----------------------------------------------------------------------
  PCB revision 3

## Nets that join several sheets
GND: AVR128DA48_Curiosity_Nano_Target_MCU (16 pins), AVR128DA48_Curiosity_Nano_Debugger (30 pins)
VBUS: AVR128DA48_Curiosity_Nano_Target_MCU (J200.56), AVR128DA48_Curiosity_Nano_Debugger (F100.1)
VCC_EDGE: AVR128DA48_Curiosity_Nano_Target_MCU (C205.1 J200.51), AVR128DA48_Curiosity_Nano_Debugger (J100.2 J101.1)
VCC_TARGET: AVR128DA48_Curiosity_Nano_Target_MCU (7 pins), AVR128DA48_Curiosity_Nano_Debugger (J101.2)
CDC_RX: AVR128DA48_Curiosity_Nano_Target_MCU (J200.3 J201.1), AVR128DA48_Curiosity_Nano_Debugger (U104.4)
CDC_TX: AVR128DA48_Curiosity_Nano_Target_MCU (J200.4 J203.1), AVR128DA48_Curiosity_Nano_Debugger (U103.4)
DBG0: AVR128DA48_Curiosity_Nano_Target_MCU (J200.53 J204.1), AVR128DA48_Curiosity_Nano_Debugger (U105.4)
DBG1: AVR128DA48_Curiosity_Nano_Target_MCU (J200.5 J205.1), AVR128DA48_Curiosity_Nano_Debugger (U106.4)
DBG2: AVR128DA48_Curiosity_Nano_Target_MCU (J200.6 J206.1), AVR128DA48_Curiosity_Nano_Debugger (U107.4)
DBG3: AVR128DA48_Curiosity_Nano_Target_MCU (J200.54 J202.1), AVR128DA48_Curiosity_Nano_Debugger (R110.2)
ID_SYS: AVR128DA48_Curiosity_Nano_Target_MCU (J200.2), AVR128DA48_Curiosity_Nano_Debugger (R112.2 U100.22)
~{VOFF}: AVR128DA48_Curiosity_Nano_Target_MCU (J200.55), AVR128DA48_Curiosity_Nano_Debugger (U100.20)

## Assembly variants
Default Assembly: all parts fitted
